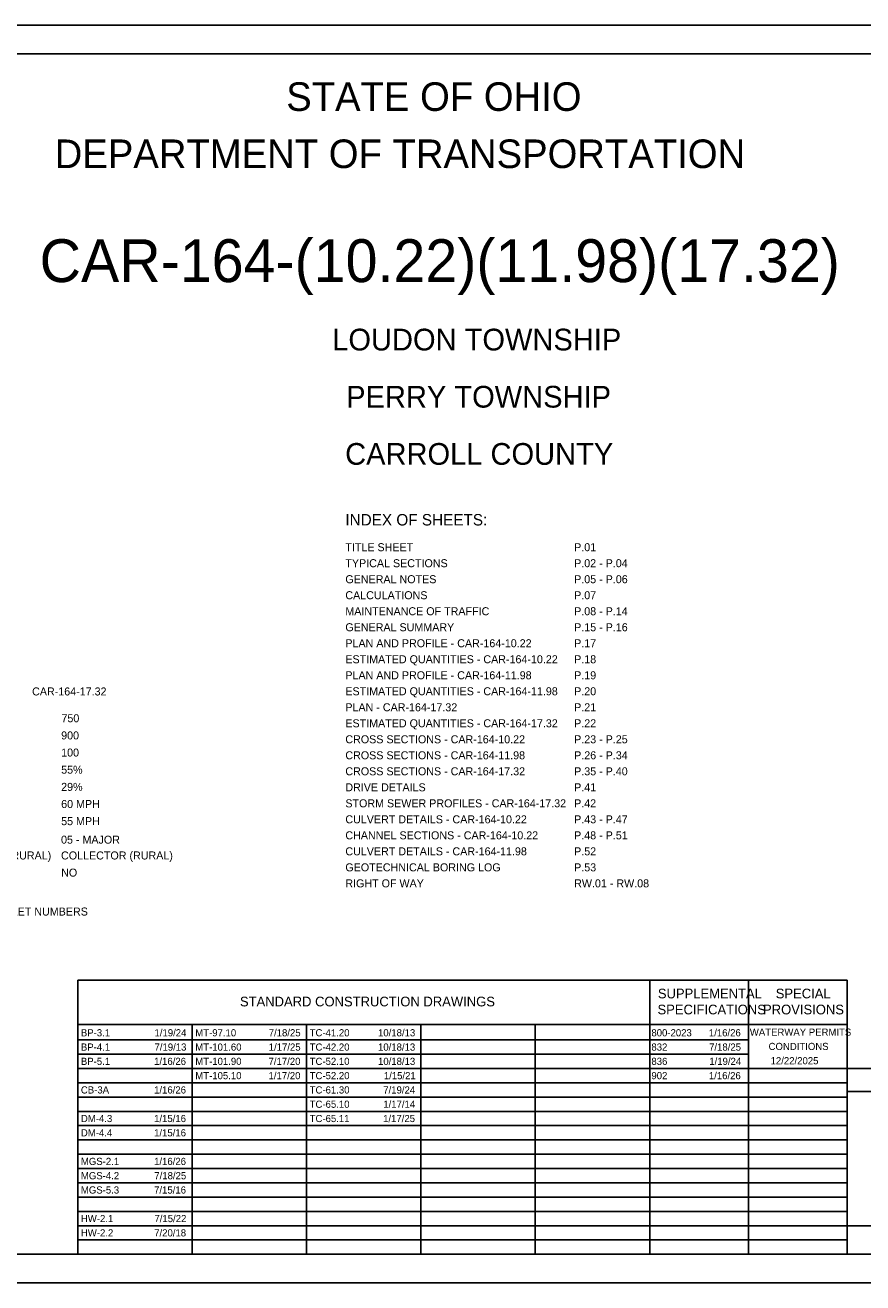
# Model space of a CAD drawing. Extents: x -3.6 to 34, y 0 to 32.8.
# Drawn here: x 9.23 to 23.88, y 0 to 22 of the extents above; entities that cross this region are included whole.
import ezdxf

# ---------------------------------------------------------------- set-up
doc = ezdxf.new("R2010")
doc.units = 0
for name, color, linetype in [('SH_Border', 7, 'Continuous'), ('SH_Cut_Line', 7, 'Continuous'), ('SH_Data', 7, 'Continuous'), ('SH_Text', 7, 'Continuous')]:
    doc.layers.add(name, color=color, linetype=linetype)

msp = doc.modelspace()

# ---------------------------------------------------------------- linework, layer by layer
at = {"layer": 'SH_Border'}
msp.add_lwpolyline([(1.5, 21.5), (33.5, 21.5), (33.5, 0.5), (1.5, 0.5)], close=True, dxfattribs=at)
at = {"layer": 'SH_Cut_Line'}
msp.add_lwpolyline([(0, 0), (34, 0), (34, 22), (0, 22)], close=True, dxfattribs=at)
at = {"layer": 'SH_Data'}
for p, q in [((10.15, 5.292), (23.6, 5.292)), ((10.15, 0.5), (10.15, 5.292)), ((20.15, 0.5), (20.15, 5.292)), ((21.875, 0.5), (21.875, 5.292)), ((23.6, 0.5), (23.6, 5.292)), ((10.15, 4.521), (23.6, 4.521)), ((12.15, 0.5), (12.15, 4.521)), ((14.15, 0.5), (14.15, 4.521)), ((16.15, 0.5), (16.15, 4.521)), ((18.15, 0.5), (18.15, 4.521)), ((10.15, 4.25), (21.875, 4.25)), ((10.15, 4), (21.875, 4)), ((10.15, 3.75), (23.6, 3.75)), ((23.6, 0.5), (23.6, 3.75)), ((23.6, 3.75), (26.4, 3.75)), ((10.15, 3.5), (23.6, 3.5)), ((23.6, 3.35), (26.4, 3.35)), ((10.15, 3.25), (23.6, 3.25)), ((10.15, 3), (23.6, 3)), ((10.15, 2.75), (23.6, 2.75)), ((10.15, 2.5), (23.6, 2.5)), ((10.15, 2.25), (23.6, 2.25)), ((10.15, 2), (23.6, 2)), ((10.15, 1.75), (23.6, 1.75)), ((10.15, 1.5), (23.6, 1.5)), ((10.15, 1.25), (23.6, 1.25)), ((10.15, 1), (23.6, 1)), ((10.15, 0.75), (23.6, 0.75)), ((23.6, 0.5), (26.4, 0.5))]:
    msp.add_line(p, q, dxfattribs=at)
msp.add_lwpolyline([(23.6, 0.5), (23.6, 1), (26.4, 1), (26.4, 0.5)], close=True, dxfattribs=at)

# ---------------------------------------------------------------- texts
at = {"layer": 'SH_Text'}
for s, height, p in [('STATE OF OHIO', 0.5, (13.795, 20.5)), ('DEPARTMENT OF TRANSPORTATION', 0.5, (9.747, 19.5)), ('CAR-164-(10.22)(11.98)(17.32)', 0.75, (9.483, 17.505)), ('   LOUDON TOWNSHIP  ', 0.38, (14.176, 16.31)), ('   PERRY TOWNSHIP   ', 0.38, (14.42, 15.31)), ('   CARROLL COUNTY   ', 0.38, (14.402, 14.31)), ('INDEX OF SHEETS:', 0.2, (14.829, 13.248)), ('TITLE SHEET', 0.14, (14.829, 12.798)), ('P.01', 0.14, (18.829, 12.798)), ('TYPICAL SECTIONS', 0.14, (14.829, 12.518)), ('P.02 - P.04', 0.14, (18.829, 12.518)), ('GENERAL NOTES', 0.14, (14.829, 12.238)), ('P.05 - P.06', 0.14, (18.829, 12.238)), ('CALCULATIONS', 0.14, (14.829, 11.958)), ('P.07', 0.14, (18.829, 11.958)), ('MAINTENANCE OF TRAFFIC', 0.14, (14.829, 11.678)), ('P.08 - P.14', 0.14, (18.829, 11.678)), ('GENERAL SUMMARY', 0.14, (14.829, 11.398)), ('P.15 - P.16', 0.14, (18.829, 11.398)), ('PLAN AND PROFILE - CAR-164-10.22', 0.14, (14.829, 11.118)), ('P.17', 0.14, (18.829, 11.118)), ('ESTIMATED QUANTITIES - CAR-164-10.22', 0.14, (14.829, 10.838)), ('P.18', 0.14, (18.829, 10.838)), ('PLAN AND PROFILE - CAR-164-11.98', 0.14, (14.829, 10.558)), ('P.19', 0.14, (18.829, 10.558)), ('CAR-164-17.32', 0.14, (9.352, 10.275)), ('ESTIMATED QUANTITIES - CAR-164-11.98', 0.14, (14.829, 10.278)), ('P.20', 0.14, (18.829, 10.278)), ('PLAN - CAR-164-17.32', 0.14, (14.829, 9.998)), ('P.21', 0.14, (18.829, 9.998)), ('750   ', 0.14, (9.865, 9.806)), ('ESTIMATED QUANTITIES - CAR-164-17.32', 0.14, (14.829, 9.718)), ('P.22', 0.14, (18.829, 9.718)), ('900   ', 0.14, (9.86, 9.506)), ('CROSS SECTIONS - CAR-164-10.22', 0.14, (14.829, 9.438)), ('P.23 - P.25', 0.14, (18.829, 9.438)), ('100   ', 0.14, (9.86, 9.206)), ('CROSS SECTIONS - CAR-164-11.98', 0.14, (14.829, 9.158)), ('P.26 - P.34', 0.14, (18.829, 9.158)), ('55%   ', 0.14, (9.86, 8.906)), ('CROSS SECTIONS - CAR-164-17.32', 0.14, (14.829, 8.878)), ('P.35 - P.40', 0.14, (18.829, 8.878)), ('29%   ', 0.14, (9.86, 8.606)), ('DRIVE DETAILS', 0.14, (14.829, 8.598)), ('P.41', 0.14, (18.829, 8.598)), ('60 MPH', 0.14, (9.86, 8.306)), ('STORM SEWER PROFILES - CAR-164-17.32', 0.14, (14.829, 8.318)), ('P.42', 0.14, (18.829, 8.318)), ('55 MPH', 0.14, (9.86, 8.006)), ('CULVERT DETAILS - CAR-164-10.22', 0.14, (14.829, 8.038)), ('P.43 - P.47', 0.14, (18.829, 8.038)), ('05 - MAJOR                                      ', 0.14, (9.858, 7.682)), ('CHANNEL SECTIONS - CAR-164-10.22', 0.14, (14.829, 7.758)), ('P.48 - P.51', 0.14, (18.829, 7.758)), ('COLLECTOR (RURAL)                               ', 0.14, (7.731, 7.406)), ('COLLECTOR (RURAL)                               ', 0.14, (9.858, 7.406)), ('CULVERT DETAILS - CAR-164-11.98', 0.14, (14.829, 7.478)), ('P.52', 0.14, (18.829, 7.478)), ('GEOTECHNICAL BORING LOG', 0.14, (14.829, 7.198)), ('P.53', 0.14, (18.829, 7.198)), ('NO    ', 0.14, (9.86, 7.106)), ('RIGHT OF WAY', 0.14, (14.829, 6.918)), ('RW.01 - RW.08', 0.14, (18.829, 6.918)), ('SHEET NUMBERS', 0.14, (8.714, 6.425)), ('SUPPLEMENTAL', 0.17, (20.293, 4.976)), ('SPECIAL', 0.17, (22.354, 4.976)), ('STANDARD CONSTRUCTION DRAWINGS', 0.17, (12.986, 4.836)), ('SPECIFICATIONS', 0.17, (20.287, 4.696)), ('PROVISIONS', 0.17, (22.132, 4.696)), ('BP-3.1', 0.125, (10.205, 4.312)), ('1/19/24', 0.125, (11.492, 4.312)), ('MT-97.10', 0.125, (12.205, 4.312)), ('7/18/25', 0.125, (13.489, 4.312)), ('TC-41.20', 0.125, (14.205, 4.312)), ('10/18/13', 0.125, (15.4, 4.312)), ('800-2023', 0.125, (20.18, 4.312)), ('1/16/26', 0.125, (21.185, 4.312)), ('WATERWAY PERMITS', 0.125, (21.901, 4.323)), ('BP-4.1', 0.125, (10.205, 4.062)), ('7/19/13', 0.125, (11.492, 4.062)), ('MT-101.60', 0.125, (12.205, 4.062)), ('1/17/25', 0.125, (13.489, 4.062)), ('TC-42.20', 0.125, (14.205, 4.062)), ('10/18/13', 0.125, (15.4, 4.062)), ('832', 0.125, (20.18, 4.062)), ('7/18/25', 0.125, (21.189, 4.062)), ('CONDITIONS', 0.125, (22.229, 4.073)), ('BP-5.1', 0.125, (10.205, 3.812)), ('1/16/26', 0.125, (11.485, 3.812)), ('MT-101.90', 0.125, (12.205, 3.812)), ('7/17/20', 0.125, (13.486, 3.812)), ('TC-52.10', 0.125, (14.205, 3.812)), ('10/18/13', 0.125, (15.4, 3.812)), ('836', 0.125, (20.18, 3.812)), ('1/19/24', 0.125, (21.192, 3.812)), ('12/22/2025', 0.125, (22.264, 3.823)), ('MT-105.10', 0.125, (12.205, 3.562)), ('1/17/20', 0.125, (13.486, 3.562)), ('TC-52.20', 0.125, (14.205, 3.562)), ('1/15/21', 0.125, (15.502, 3.562)), ('902', 0.125, (20.18, 3.562)), ('1/16/26', 0.125, (21.185, 3.562)), ('CB-3A', 0.125, (10.205, 3.312)), ('1/16/26', 0.125, (11.485, 3.312)), ('TC-61.30', 0.125, (14.205, 3.312)), ('7/19/24', 0.125, (15.492, 3.312)), ('TC-65.10', 0.125, (14.205, 3.062)), ('1/17/14', 0.125, (15.492, 3.062)), ('DM-4.3', 0.125, (10.205, 2.812)), ('1/15/16', 0.125, (11.485, 2.812)), ('TC-65.11', 0.125, (14.205, 2.812)), ('1/17/25', 0.125, (15.489, 2.812)), ('DM-4.4', 0.125, (10.205, 2.562)), ('1/15/16', 0.125, (11.485, 2.562)), ('MGS-2.1', 0.125, (10.205, 2.062)), ('1/16/26', 0.125, (11.485, 2.062)), ('MGS-4.2', 0.125, (10.205, 1.812)), ('7/18/25', 0.125, (11.489, 1.812)), ('MGS-5.3', 0.125, (10.205, 1.562)), ('7/15/16', 0.125, (11.485, 1.562)), ('HW-2.1', 0.125, (10.205, 1.062)), ('7/15/22', 0.125, (11.491, 1.062)), ('HW-2.2', 0.125, (10.205, 0.812)), ('7/20/18', 0.125, (11.487, 0.812))]:
    msp.add_text(s, height=height, dxfattribs=at).set_placement(p)

doc.saveas('drawing.dxf')
